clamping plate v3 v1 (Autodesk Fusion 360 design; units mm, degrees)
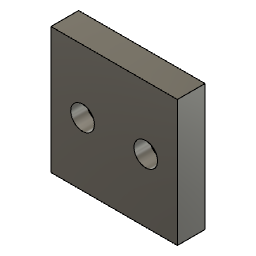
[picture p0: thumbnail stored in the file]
sketch "Sketch1" plane through (0, 0, 0) normal (0, 0, 1) x axis (1, 0, 0)
  line L1 (-16, -16) -> (16, -16)
  line L2 (-16, 16) -> (-16, -16)
  line L3 (16, 16) -> (-16, 16)
  line L4 (16, -16) -> (16, 16)
  line L5 (-16, 16) -> (16, -16)
  line L6 (16, 16) -> (-16, -16)
  line L7 (21.4207, 0) -> (-21.4766, 0)
  point P6 (0, 0)
  point P1 (0, 0)
  point P9 (-8, 0)
  point P10 (8, 0)
  point P4 (-16, 16)
  point P5 (16, 16)
  point P3 (-16, -16)
  perpendicular L1 L2
  parallel L1 L3
  parallel L2 L4
  horizontal L1
  coincident L5 P6
  coincident L6 P6
  coincident P1 P6
  perpendicular L4 L7
  coincident L7 P9
  coincident L7 P10
  dimension "d1" distance P4 P5 = 32
  dimension "d2" distance P3 P4 = 32
  dimension "d3" distance L2 P9 = 8
  dimension "d4" distance P9 P10 = 16
extrude "Extrude1" new body sketch "Sketch1" profile of L1 L2 L3 L4 along normal blind 7
hole "Hole1" HoleDepth 7 HoleDiameter 6 TipAngle 119 CSDiameter 12 CSAngle 90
